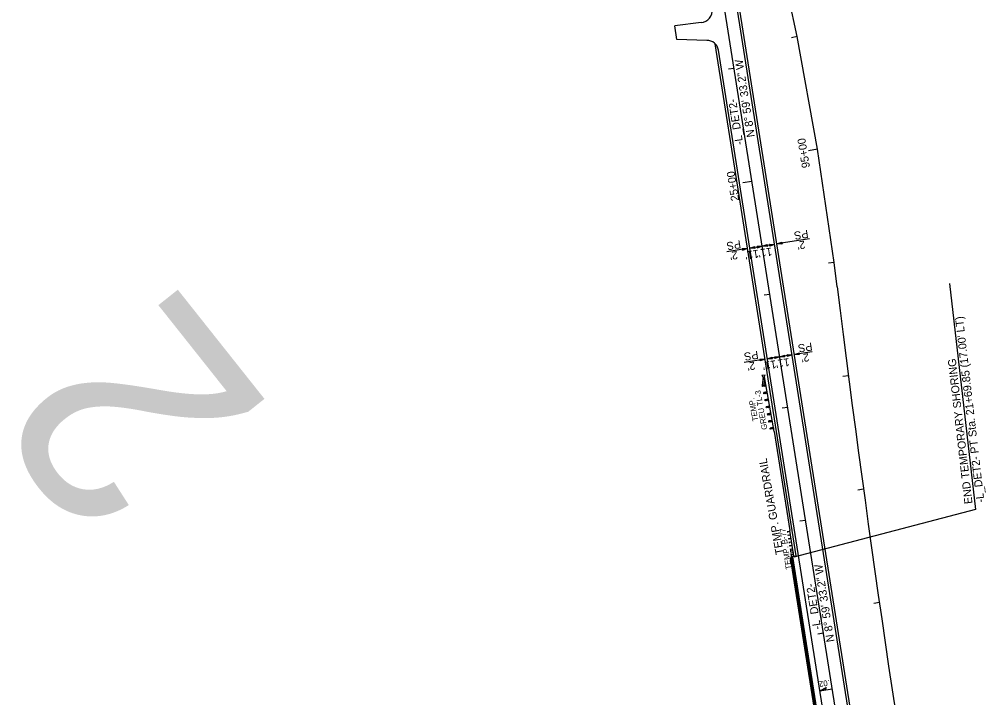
# Model space of a CAD drawing. Extents: x 473658 to 481584, y 489119 to 506230.
# Drawn here: x 477584 to 478429, y 495645 to 496238 of the extents above; entities that cross this region are included whole.
import ezdxf

# ---------------------------------------------------------------- set-up
doc = ezdxf.new("R2010")
doc.units = 0
for name, color, linetype in [('Exist Structure Minor Culvert Topo', 7, 'Continuous'), ('Exist Structure Minor Pipes CMP 60 Inch', 7, 'Continuous'), ('Prop Conc Barrier', 7, 'Continuous'), ('Prop Dimension', 7, 'Continuous'), ('Prop EOT', 7, 'Continuous'), ('Prop Guardrail', 7, 'Continuous'), ('Prop Guardrail Anchor Unit CELL', 7, 'Continuous'), ('Prop Horizontal Alignment', 7, 'Continuous'), ('Prop Horizontal Alignment Direction Label', 7, 'Continuous'), ('Prop Horizontal Alignment Station Label', 7, 'Continuous'), ('Prop Horizontal Alignment Tick Label', 7, 'Continuous'), ('Prop Horizontal Alignment Tick Large', 7, 'Continuous'), ('Prop Horizontal Alignment Tick Small', 7, 'Continuous'), ('Prop Paved Shoulder', 7, 'Continuous'), ('Prop Superelevation  Arrow CELL', 7, 'Continuous'), ('Prop Superelevation Label', 7, 'Continuous'), ('Sheet Block Title CELL', 7, 'Continuous'), ('Sheet Profile Grid Major CELL', 7, 'Continuous')]:
    doc.layers.add(name, color=color, linetype=linetype)

msp = doc.modelspace()

# ---------------------------------------------------------------- linework, layer by layer
at = {"layer": 'Exist Structure Minor Culvert Topo'}
for p, q in [((478255.7, 495789.19), (478255.52, 495790.33)), ((478257.59, 495790.07), (478255.61, 495789.76)), ((478256.19, 495786.11), (478256.01, 495787.24)), ((478258.08, 495786.99), (478256.1, 495786.67)), ((478261.01, 495768.47), (478257.43, 495791.06)), ((478256.68, 495783.02), (478256.5, 495784.15)), ((478258.56, 495783.9), (478256.59, 495783.59)), ((478257.17, 495779.93), (478256.99, 495781.07)), ((478259.05, 495780.81), (478257.08, 495780.5)), ((478257.66, 495776.85), (478257.48, 495777.98)), ((478259.54, 495777.73), (478257.57, 495777.41)), ((478258.14, 495773.76), (478257.96, 495774.89)), ((478260.03, 495774.64), (478258.05, 495774.33)), ((478258.39, 495772.22), (478258.21, 495773.35)), ((478260.27, 495773.1), (478258.3, 495772.78)), ((478258.63, 495770.67), (478258.45, 495771.81)), ((478260.52, 495771.55), (478258.54, 495771.24)), ((478258.88, 495769.13), (478258.7, 495770.26)), ((478260.76, 495770.01), (478258.79, 495769.7)), ((478259.12, 495767.59), (478258.94, 495768.72)), ((478261.01, 495768.47), (478259.03, 495768.15))]:
    msp.add_line(p, q, dxfattribs=at)
at = {"layer": 'Exist Structure Minor Pipes CMP 60 Inch'}
msp.add_line((478291.29, 495557.58), (478258.12, 495767.21), dxfattribs=at)
at = {"layer": 'Prop Conc Barrier'}
msp.add_line((478293.31, 495557.93), (478260.02, 495768.31), dxfattribs=at)
at = {"layer": 'Prop Dimension'}
for p, q in [((478244.14, 496041.06), (478222.41, 496037.62)), ((478274.71, 496045.9), (478246.12, 496041.37)), ((478220.44, 496037.31), (478202.2, 496034.42)), ((478277.07, 495947.24), (478261.41, 495944.76)), ((478235.73, 495940.7), (478217.48, 495937.81)), ((478259.43, 495944.45), (478237.7, 495941.01))]:
    msp.add_line(p, q, dxfattribs=at)
for points in [[(478226.98, 496037.56), (478222.41, 496037.62), (478226.76, 496039.12), (478226.31, 496038.24)], [(478228.71, 496039.4), (478233.28, 496039.34), (478228.93, 496037.84), (478229.38, 496038.72)], [(478237.84, 496039.28), (478233.28, 496039.34), (478237.62, 496040.84), (478237.18, 496039.96)], [(478239.58, 496041.12), (478244.14, 496041.06), (478239.8, 496039.56), (478240.24, 496040.44)], [(478250.68, 496041.31), (478246.12, 496041.37), (478250.46, 496042.87), (478250.02, 496041.99)], [(478215.87, 496037.37), (478220.44, 496037.31), (478216.09, 496035.81), (478216.54, 496036.69)], [(478265.97, 495944.7), (478261.41, 495944.76), (478265.75, 495946.26), (478265.31, 495945.38)], [(478231.16, 495940.76), (478235.73, 495940.7), (478231.38, 495939.2), (478231.82, 495940.08)], [(478242.27, 495940.95), (478237.7, 495941.01), (478242.05, 495942.51), (478241.6, 495941.63)], [(478244, 495942.79), (478248.57, 495942.73), (478244.22, 495941.23), (478244.66, 495942.11)], [(478253.13, 495942.67), (478248.57, 495942.73), (478252.91, 495944.22), (478252.47, 495943.34)], [(478254.87, 495944.51), (478259.43, 495944.45), (478255.09, 495942.95), (478255.53, 495943.83)]]:
    msp.add_lwpolyline(points, close=True, dxfattribs=at)
at = {"layer": 'Prop EOT'}
for p, q in [((478319.94, 495562.11), (478181.82, 496434.86)), ((478179.82, 496235.09), (478156.72, 496231.98)), ((478158.58, 496220.23), (478156.72, 496231.98)), ((478184.76, 496219.26), (478158.58, 496220.23)), ((478298.21, 495558.67), (478195, 496210.83))]:
    msp.add_line(p, q, dxfattribs=at)
for centre, start, end in [((478179.46, 496245.08), 272.07602, 8.99254), ((478185.12, 496209.27), 8.99254, 92.07602)]:
    msp.add_arc(centre, 10, start, end, dxfattribs=at)
at = {"layer": 'Prop Guardrail'}
msp.add_line((478243.75, 495877.48), (478257.43, 495791.06), dxfattribs=at)
at = {"layer": 'Prop Guardrail Anchor Unit CELL'}
for p, q in [((478235.79, 495926.84), (478232.88, 495926.38)), ((478232.88, 495926.38), (478233.91, 495925.35)), ((478233.46, 495917.65), (478234.14, 495922.75)), ((478233.91, 495925.35), (478234.24, 495923.33)), ((478235.44, 495924), (478233.96, 495923.73)), ((478234.14, 495922.75), (478233.96, 495923.73)), ((478233.96, 495923.73), (478235.61, 495923.01)), ((478234.14, 495922.75), (478234.05, 495923.24)), ((478235.44, 495924), (478234.14, 495922.75)), ((478235.61, 495923.01), (478234.14, 495922.75)), ((478234.24, 495923.33), (478234.84, 495923.43)), ((478234.84, 495923.43), (478235.44, 495923.52)), ((478234.97, 495917.92), (478235.61, 495923.01)), ((478235.12, 495925.55), (478235.79, 495926.84)), ((478235.44, 495923.52), (478235.12, 495925.55)), ((478243.75, 495877.48), (478235.52, 495923.51)), ((478236.48, 495918.19), (478233.46, 495917.65)), ((478233.64, 495916.67), (478233.46, 495917.65)), ((478233.46, 495917.65), (478235.14, 495916.94)), ((478234.97, 495917.92), (478233.64, 495916.67)), ((478236.65, 495917.2), (478233.64, 495916.67)), ((478237.58, 495911.99), (478234.63, 495911.46)), ((478236.11, 495911.72), (478234.81, 495910.47)), ((478235.14, 495916.94), (478234.97, 495917.92)), ((478236.65, 495917.2), (478234.97, 495917.92)), ((478235.14, 495916.94), (478236.48, 495918.19)), ((478236.28, 495910.74), (478236.11, 495911.72)), ((478237.76, 495911), (478236.11, 495911.72)), ((478236.28, 495910.74), (478237.58, 495911.99)), ((478234.81, 495910.47), (478234.63, 495911.46)), ((478234.63, 495911.46), (478236.28, 495910.74)), ((478237.76, 495911), (478234.81, 495910.47)), ((478238.69, 495905.78), (478235.61, 495905.23)), ((478235.78, 495904.25), (478235.61, 495905.23)), ((478235.61, 495905.23), (478237.33, 495904.52)), ((478237.15, 495905.51), (478235.78, 495904.25)), ((478238.87, 495904.8), (478235.78, 495904.25)), ((478237.33, 495904.52), (478237.15, 495905.51)), ((478238.87, 495904.8), (478237.15, 495905.51)), ((478237.33, 495904.52), (478238.69, 495905.78)), ((478239.8, 495899.58), (478236.81, 495899.05)), ((478236.99, 495898.06), (478236.81, 495899.05)), ((478236.81, 495899.05), (478238.48, 495898.33)), ((478238.31, 495899.31), (478236.99, 495898.06)), ((478239.98, 495898.6), (478236.99, 495898.06)), ((478238.48, 495898.33), (478238.31, 495899.31)), ((478239.98, 495898.6), (478238.31, 495899.31)), ((478238.48, 495898.33), (478239.8, 495899.58)), ((478239.98, 495898.6), (478239.8, 495899.58)), ((478240.91, 495893.38), (478237.91, 495892.84)), ((478238.09, 495891.86), (478237.91, 495892.84)), ((478237.91, 495892.84), (478239.59, 495892.13)), ((478239.41, 495893.11), (478238.09, 495891.86)), ((478241.09, 495892.39), (478238.09, 495891.86)), ((478242.02, 495887.17), (478239.02, 495886.64)), ((478239.19, 495885.65), (478239.02, 495886.64)), ((478239.02, 495886.64), (478240.69, 495885.92)), ((478240.52, 495886.91), (478239.19, 495885.65)), ((478239.59, 495892.13), (478239.41, 495893.11)), ((478241.09, 495892.39), (478239.41, 495893.11)), ((478239.59, 495892.13), (478240.91, 495893.38)), ((478240.69, 495885.92), (478240.52, 495886.91)), ((478242.2, 495886.19), (478240.52, 495886.91)), ((478240.69, 495885.92), (478242.02, 495887.17)), ((478242.2, 495886.19), (478239.19, 495885.65)), ((478243.13, 495880.97), (478240.18, 495880.44)), ((478240.35, 495879.46), (478240.18, 495880.44)), ((478240.18, 495880.44), (478241.83, 495879.72)), ((478241.65, 495880.71), (478240.35, 495879.46)), ((478243.31, 495879.99), (478240.35, 495879.46)), ((478243.13, 495880.97), (478241.65, 495880.71)), ((478241.83, 495879.72), (478241.65, 495880.71)), ((478241.65, 495880.71), (478243.31, 495879.99)), ((478241.83, 495879.72), (478243.13, 495880.97)), ((478243.31, 495879.99), (478243.13, 495880.97))]:
    msp.add_line(p, q, dxfattribs=at)
at = {"layer": 'Prop Horizontal Alignment'}
for p, q in [((478309.07, 495560.39), (478170.96, 496433.14)), ((478263.69, 496222.6), (478254.85, 496265.39)), ((478281.57, 496124.22), (478263.69, 496222.6)), ((478296.16, 496025.29), (478281.57, 496124.22)), ((478298.87, 496003.86), (478296.16, 496025.29))]:
    msp.add_line(p, q, dxfattribs=at)
msp.add_arc((491911.02, 497680.41), 13715, 187.021509, 189.816184, dxfattribs=at)
at = {"layer": 'Prop Horizontal Alignment Station Label'}
for p, q in [((478396.97, 496006.89), (478419.86, 495809.33)), ((478419.86, 495809.33), (478261.05, 495767.67))]:
    msp.add_line(p, q, dxfattribs=at)
at = {"layer": 'Prop Horizontal Alignment Tick Large'}
for p, q in [((478281.57, 496124.22), (478273.67, 496122.92)), ((478224.29, 496096.11), (478216.39, 496094.86))]:
    msp.add_line(p, q, dxfattribs=at)
at = {"layer": 'Prop Horizontal Alignment Tick Small'}
for p, q in [((478263.69, 496222.6), (478258.79, 496221.62)), ((478208.66, 496194.88), (478203.72, 496194.1)), ((478296.16, 496025.29), (478291.2, 496024.64)), ((478239.92, 495997.34), (478234.98, 495996.56)), ((478308.68, 495926.08), (478303.72, 495925.44)), ((478255.55, 495898.57), (478250.62, 495897.79)), ((478321.83, 495826.95), (478316.88, 495826.27)), ((478271.18, 495799.8), (478266.25, 495799.02)), ((478335.71, 495727.91), (478330.76, 495727.2)), ((478286.82, 495701.03), (478281.88, 495700.25))]:
    msp.add_line(p, q, dxfattribs=at)
at = {"layer": 'Prop Paved Shoulder'}
for p, q in [((478321.91, 495562.42), (478183.8, 496435.17)), ((478262.93, 495768.77), (478192.09, 496216.44)), ((478258.98, 495768.15), (478262.93, 495768.77)), ((478292.28, 495557.74), (478258.98, 495768.15))]:
    msp.add_line(p, q, dxfattribs=at)
at = {"layer": 'Prop Superelevation  Arrow CELL'}
msp.add_lwpolyline([(478283.62, 495650.84), (478289.23, 495653.76), (478288.19, 495651.57)], close=True, dxfattribs=at)
at = {"layer": 'Prop Superelevation Label'}
msp.add_line((478283.62, 495650.84), (478294.49, 495652.56), dxfattribs=at)

# ---------------------------------------------------------------- texts
at = {"layer": 'Prop Dimension'}
for s, p in [('PS', (478273.03, 496053.83)), ('PS', (478214.05, 496044.69)), ("2'", (478270.28, 496044.41)), ("2'", (478211.3, 496035.27)), ("11'", (478229.8, 496036.48)), ("11'", (478241.38, 496038.31)), ('PS', (478276.52, 495955.35)), ('PS', (478229.34, 495948.08)), ("2'", (478273.76, 495945.93)), ("2'", (478226.59, 495938.66)), ("11'", (478245.09, 495939.87)), ("11'", (478256.67, 495941.7))]:
    msp.add_text(s, height=7, rotation=188.99254, dxfattribs=at).set_placement(p)
at = {"layer": 'Prop Guardrail Anchor Unit CELL'}
for s, rotation, p in [('GREU TL-3', 100.12559, (478237.83, 495879.45)), ('TEMP. ', 100.12559, (478229.83, 495886.98)), ('TEMP. B-77', 98.63849, (478258.96, 495757.25))]:
    msp.add_text(s, height=5, rotation=rotation, dxfattribs=at).set_placement(p)
at = {"layer": 'Prop Horizontal Alignment Direction Label'}
for s, p in [('N 8%%d 59\' 33.2" W', (478226.87, 496135.23)), ('-L_DET2-', (478216.68, 496128.45)), ('N 8%%d 59\' 33.2" W', (478296.45, 495693.92)), ('-L_DET2-', (478284.74, 495704.9))]:
    msp.add_text(s, height=7, rotation=98.99254, dxfattribs=at).set_placement(p)
at = {"layer": 'Prop Horizontal Alignment Station Label'}
for s, p in [("-L_DET2- PT Sta. 21+69.85 (17.00' LT)", (478427.58, 495815.71)), ('END TEMPORARY SHORING', (478417.15, 495814.5))]:
    msp.add_text(s, height=7, rotation=96.60736, dxfattribs=at).set_placement(p)
at = {"layer": 'Prop Horizontal Alignment Tick Label'}
for s, rotation, p in [('95+00', 99.34389, (478275.05, 496108.4)), ('25+00', 98.99254, (478213.09, 496079.47))]:
    msp.add_text(s, height=7, rotation=rotation, dxfattribs=at).set_placement(p)
at = {"layer": 'Prop Superelevation Label'}
msp.add_text('.02', height=5, rotation=188.9925, dxfattribs=at).set_placement((478291.85, 495660.38))
at = {"layer": 'Sheet Block Title CELL'}
msp.add_text('2', height=200, rotation=128.44881, dxfattribs=at).set_placement((477806.4, 495895.44))
at = {"layer": 'Sheet Profile Grid Major CELL'}
for s, p in [('GUARDRAIL', (478246.68, 495800.77)), ('TEMP. ', (478252.08, 495770.49))]:
    msp.add_text(s, height=7, rotation=100.12493, dxfattribs=at).set_placement(p)

doc.saveas('drawing.dxf')
